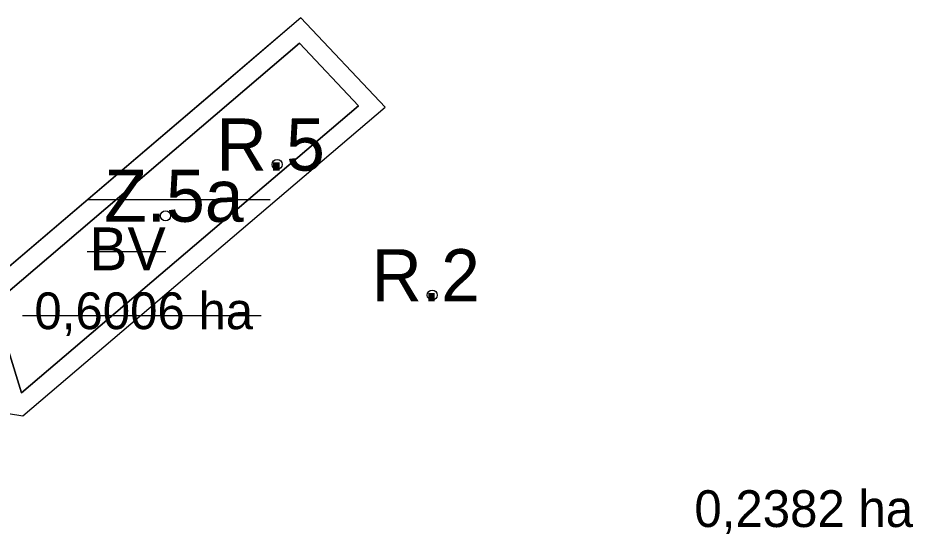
# Model space of a CAD drawing. Extents: x -554894 to -553703, y -1185789 to -1185042.
# Drawn here: x -554624.2 to -554332, y -1185486.7 to -1185321.5 of the extents above; entities that cross this region are included whole.
import ezdxf

# ---------------------------------------------------------------- set-up
doc = ezdxf.new("R2010")
doc.units = 0
for name, color, linetype in [('BILA_TECKA', 7, 'Continuous'), ('ID_navrh', 7, 'Continuous'), ('KRIZEK_ke_zruseni', 7, 'Continuous'), ('LEG_prac_vykres_ZPF', 7, 'Continuous'), ('REGULATIV_navrh', 7, 'Continuous'), ('rezerva_BV', 7, 'Continuous'), ('upusteno_platny_UP', 7, 'Continuous'), ('vymery', 7, 'Continuous')]:
    doc.layers.add(name, color=color, linetype=linetype)

msp = doc.modelspace()

# ---------------------------------------------------------------- linework, layer by layer
at = {"layer": 'BILA_TECKA'}
for centre in [(-554539.54, -1185369.3), (-554575.95, -1185386.1), (-554488.92, -1185411.96)]:
    msp.add_circle(centre, 1.64, dxfattribs=at)
at = {"layer": 'KRIZEK_ke_zruseni'}
for p, q in [((-554601.46, -1185380.76), (-554541.86, -1185380.76)), ((-554601.6, -1185397.76), (-554575.89, -1185397.76))]:
    msp.add_line(p, q, dxfattribs=at)
at = {"layer": 'LEG_prac_vykres_ZPF'}
msp.add_lwpolyline([(-554513, -1185350.16), (-554532.23, -1185329.76), (-554632.02, -1185414.79), (-554622.99, -1185443.89), (-554513, -1185350.16)], dxfattribs=at)
at = {"layer": 'rezerva_BV'}
for p, q in [((-554531.78, -1185321.49), (-554638.92, -1185412.79)), ((-554504.31, -1185350.64), (-554531.78, -1185321.49)), ((-554622.56, -1185451.39), (-554504.31, -1185350.64))]:
    msp.add_line(p, q, dxfattribs=at)
for points in [[(-554622.99, -1185443.89), (-554632.02, -1185414.79), (-554532.23, -1185329.76), (-554513, -1185350.16), (-554622.99, -1185443.89)], [(-554638.92, -1185412.79), (-554627.18, -1185450.64), (-554622.56, -1185451.39)]]:
    msp.add_lwpolyline(points, dxfattribs=at)
at = {"layer": 'upusteno_platny_UP'}
msp.add_line((-554504.31, -1185350.64), (-554531.78, -1185321.49), dxfattribs=at)
for points in [[(-554531.78, -1185321.49), (-554556.23, -1185342.33), (-554638.92, -1185412.79)], [(-554638.92, -1185412.79), (-554627.18, -1185450.64), (-554622.56, -1185451.39), (-554504.31, -1185350.64)]]:
    msp.add_lwpolyline(points, dxfattribs=at)
at = {"layer": 'vymery'}
msp.add_line((-554622.7, -1185418.61), (-554544.71, -1185418.61), dxfattribs=at)

# ---------------------------------------------------------------- texts
at = {"layer": 'ID_navrh'}
for s, p in [('R.5', (-554559.36, -1185371.32)), ('Z.5a', (-554596, -1185388.04)), ('R.2', (-554508.74, -1185413.97))]:
    msp.add_text(s, height=17, dxfattribs=at).set_placement(p)
at = {"layer": 'REGULATIV_navrh'}
msp.add_text('BV', height=14, dxfattribs=at).set_placement((-554600.89, -1185403.87))
at = {"layer": 'vymery'}
for s, p in [('0,6006 ha', (-554618.77, -1185423.09)), ('0,2382 ha', (-554403.35, -1185487.65))]:
    msp.add_text(s, height=12, dxfattribs=at).set_placement(p)

doc.saveas('drawing.dxf')
